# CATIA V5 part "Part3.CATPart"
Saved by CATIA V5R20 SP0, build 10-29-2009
Part number: Part1.1
Bounding box of the stored display mesh (mm): x -15.011 to 15.011, y -13 to 13, z 0 to 12
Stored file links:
  C:\Users\hojat azimi\Desktop\New folder\Part3.CATPart
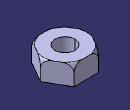
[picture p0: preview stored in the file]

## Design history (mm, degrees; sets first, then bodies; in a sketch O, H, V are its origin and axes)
Body1 (main body)
  Sketch1 on xy-plane, origin (0, 0, 0), H (1, 0, 0), V (0, 1, 0)
    line L1 (7.5056, 13) -> (0, 13)
    line L2 (-7.5056, 13) -> (-11.2583, 6.5)
    line L3 (-15.0111, 0) -> (-11.2583, -6.5)
    line L4 (-7.5056, -13) -> (0, -13)
    line L5 (7.5056, -13) -> (11.2583, -6.5)
    line L6 (15.0111, 0) -> (11.2583, 6.5)
    construction line L7 (0, 0) -> (0, 13)
    circle A1 centre (0, 0) radius 6
    arc A2 centre (0, 0) radius 13 from (-11.2583, -6.5) to (0, -13) ccw
    line L8 (0, -13) -> (7.5056, -13)
    line L9 (11.2583, -6.5) -> (15.0111, 0)
    point P10 (11.2583, 6.5)
    line L10 (11.2583, 6.5) -> (7.5056, 13)
    line L11 (0, 13) -> (-7.5056, 13)
    point P12 (-11.2583, 6.5)
    line L12 (-11.2583, 6.5) -> (-15.0111, 0)
    line L13 (-11.2583, -6.5) -> (-7.5056, -13)
    arc A3 centre (0, 0) radius 13 from (0, -13) to (11.2583, -6.5) ccw
    arc A4 centre (0, 0) radius 13 from (11.2583, -6.5) to (11.2583, 6.5) ccw
    point P15 (11.2583, 6.5)
    arc A5 centre (0, 0) radius 13 from (11.2583, 6.5) to (0, 13) ccw
    arc A6 centre (0, 0) radius 13 from (0, 13) to (-11.2583, 6.5) ccw
    point P16 (-11.2583, 6.5)
    arc A7 centre (0, 0) radius 13 from (-11.2583, 6.5) to (-11.2583, -6.5) ccw
    coincidence: P10 P15, P12 P16
  MultiPad1: profile Sketch1, domains (length 12; length 12; length 12; length 12; length 12; length 12; length 12; length 0)
  Sketch2 on face of MultiPad1, origin (11.2583, 6.5, 0), H (-0.5, 0.866, 0), V (0, 0, 1)
    arc A1 centre (2.5056, 7) radius 5 from (7.5056, 7) to (2.5056, 12) ccw
    line L1 (2.5056, 12) -> (9.7205, 17.3163)
    line L2 (9.7205, 17.3163) -> (7.5056, 7)
  Groove1: profile Sketch2, axis axis of face of MultiPad1 from Sketch1.A1, angle 360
